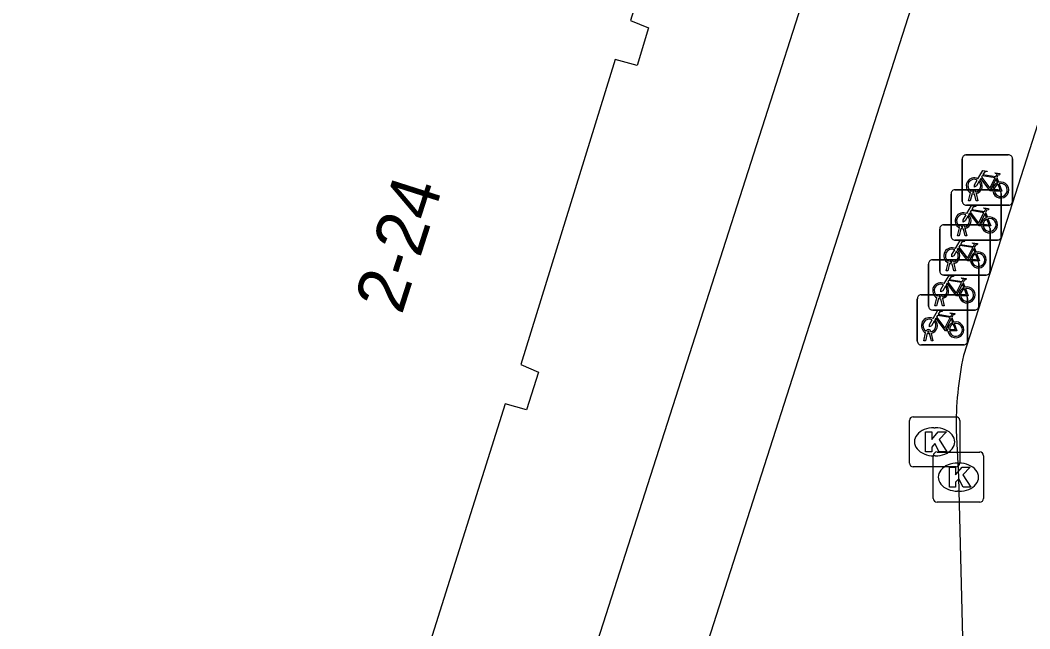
# Model space of a CAD drawing. Extents: x 160676 to 161153, y 383244 to 383713.
# Drawn here: x 161088.71 to 161108.8, y 383397.89 to 383410.01 of the extents above; entities that cross this region are included whole.
import ezdxf

# ---------------------------------------------------------------- set-up
doc = ezdxf.new("R2010")
doc.units = 0
for name, color, linetype in [('IMGEO_Fietsenrek', 7, 'Continuous'), ('IMGEO_Fietspad_gesloten', 7, 'Continuous'), ('IMGEO_Kolk', 7, 'Continuous'), ('IMGEO_Pand', 7, 'Continuous'), ('IMGEO_Pand_nummerreeks', 7, 'Continuous'), ('IMGEO_Rijbaan_lokaal_gesloten', 7, 'Continuous')]:
    doc.layers.add(name, color=color, linetype=linetype)

msp = doc.modelspace()

# ---------------------------------------------------------------- linework, layer by layer
at = {"layer": 'IMGEO_Fietsenrek'}
for p, q in [((161107.532, 383407.329), (161108.373, 383407.329)), ((161108.373, 383407.329), (161107.532, 383407.329)), ((161107.457, 383406.404), (161107.457, 383407.245)), ((161107.457, 383407.245), (161107.457, 383406.404)), ((161108.457, 383407.254), (161108.457, 383406.413)), ((161108.457, 383406.413), (161108.457, 383407.254)), ((161108.144, 383406.878), (161108.18, 383406.783)), ((161107.234, 383405.708), (161107.234, 383406.549)), ((161107.234, 383406.549), (161107.234, 383405.708)), ((161107.309, 383406.633), (161108.15, 383406.633)), ((161108.15, 383406.633), (161107.309, 383406.633)), ((161107.584, 383406.413), (161107.623, 383406.573)), ((161107.653, 383406.561), (161107.618, 383406.413)), ((161107.695, 383406.585), (161107.694, 383406.589)), ((161107.736, 383406.413), (161107.702, 383406.555)), ((161107.726, 383406.596), (161107.727, 383406.589)), ((161107.734, 383406.559), (161107.769, 383406.413)), ((161108.234, 383406.558), (161108.234, 383405.717)), ((161108.234, 383405.717), (161108.234, 383406.558)), ((161108.382, 383406.329), (161107.541, 383406.329)), ((161107.541, 383406.329), (161108.382, 383406.329)), ((161107.618, 383406.413), (161107.584, 383406.413)), ((161107.769, 383406.413), (161107.736, 383406.413)), ((161107.921, 383406.182), (161107.957, 383406.087)), ((161107.085, 383405.937), (161107.926, 383405.937)), ((161107.926, 383405.937), (161107.085, 383405.937)), ((161107.472, 383405.889), (161107.471, 383405.893)), ((161107.503, 383405.9), (161107.504, 383405.893)), ((161107.01, 383405.012), (161107.01, 383405.853)), ((161107.01, 383405.853), (161107.01, 383405.012)), ((161107.361, 383405.717), (161107.4, 383405.877)), ((161107.395, 383405.717), (161107.361, 383405.717)), ((161107.43, 383405.865), (161107.395, 383405.717)), ((161107.513, 383405.717), (161107.479, 383405.859)), ((161107.511, 383405.863), (161107.546, 383405.717)), ((161107.546, 383405.717), (161107.513, 383405.717)), ((161108.01, 383405.862), (161108.01, 383405.021)), ((161108.01, 383405.021), (161108.01, 383405.862)), ((161108.159, 383405.633), (161107.318, 383405.633)), ((161107.318, 383405.633), (161108.159, 383405.633)), ((161107.697, 383405.486), (161107.733, 383405.391)), ((161106.787, 383404.315), (161106.787, 383405.156)), ((161106.787, 383405.156), (161106.787, 383404.315)), ((161106.862, 383405.24), (161107.703, 383405.24)), ((161107.703, 383405.24), (161106.862, 383405.24)), ((161107.137, 383405.021), (161107.176, 383405.181)), ((161107.206, 383405.169), (161107.171, 383405.021)), ((161107.248, 383405.193), (161107.247, 383405.197)), ((161107.289, 383405.021), (161107.255, 383405.163)), ((161107.279, 383405.204), (161107.28, 383405.197)), ((161107.287, 383405.167), (161107.322, 383405.021)), ((161107.787, 383405.165), (161107.787, 383404.324)), ((161107.787, 383404.324), (161107.787, 383405.165)), ((161107.935, 383404.937), (161107.094, 383404.937)), ((161107.094, 383404.937), (161107.935, 383404.937)), ((161107.171, 383405.021), (161107.137, 383405.021)), ((161107.322, 383405.021), (161107.289, 383405.021)), ((161107.474, 383404.789), (161107.51, 383404.694)), ((161106.638, 383404.544), (161107.479, 383404.544)), ((161107.479, 383404.544), (161106.638, 383404.544)), ((161106.914, 383404.324), (161106.953, 383404.484)), ((161107.025, 383404.496), (161107.024, 383404.5)), ((161107.056, 383404.507), (161107.057, 383404.5)), ((161106.563, 383403.619), (161106.563, 383404.46)), ((161106.563, 383404.46), (161106.563, 383403.619)), ((161106.948, 383404.324), (161106.914, 383404.324)), ((161106.983, 383404.472), (161106.948, 383404.324)), ((161107.066, 383404.324), (161107.032, 383404.466)), ((161107.064, 383404.47), (161107.099, 383404.324)), ((161107.099, 383404.324), (161107.066, 383404.324)), ((161107.563, 383404.469), (161107.563, 383403.628)), ((161107.563, 383403.628), (161107.563, 383404.469)), ((161107.712, 383404.24), (161106.871, 383404.24)), ((161106.871, 383404.24), (161107.712, 383404.24)), ((161107.25, 383404.093), (161107.286, 383403.998)), ((161106.69, 383403.628), (161106.729, 383403.788)), ((161106.759, 383403.776), (161106.724, 383403.628)), ((161106.801, 383403.8), (161106.8, 383403.804)), ((161106.842, 383403.628), (161106.808, 383403.77)), ((161106.832, 383403.811), (161106.833, 383403.804)), ((161106.84, 383403.774), (161106.875, 383403.628)), ((161107.488, 383403.544), (161106.647, 383403.544)), ((161106.647, 383403.544), (161107.488, 383403.544)), ((161106.724, 383403.628), (161106.69, 383403.628)), ((161106.875, 383403.628), (161106.842, 383403.628))]:
    msp.add_line(p, q, dxfattribs=at)
for points in [[(161107.77, 383406.855), (161107.865, 383407.019), (161107.951, 383407.005), (161107.953, 383406.996), (161107.897, 383406.985), (161107.87, 383406.94), (161108.126, 383406.899)], [(161108.113, 383406.874), (161107.856, 383406.915), (161107.839, 383406.886), (161108.006, 383406.666), (161108.113, 383406.874)], [(161108.126, 383406.899), (161108.151, 383406.948), (161108.145, 383406.952), (161108.122, 383406.956), (161108.11, 383406.963), (161108.109, 383406.966), (161108.111, 383406.971), (161108.206, 383406.956), (161108.208, 383406.946), (161108.198, 383406.933), (161108.186, 383406.927), (161108.172, 383406.933), (161108.144, 383406.878)], [(161107.791, 383406.803), (161107.739, 383406.713), (161107.699, 383406.688), (161107.7, 383406.735), (161107.755, 383406.829)], [(161108.066, 383406.611), (161108.016, 383406.611), (161107.825, 383406.862), (161107.806, 383406.83)], [(161108.161, 383406.776), (161108.131, 383406.853), (161108.022, 383406.635), (161108.065, 383406.635)], [(161108.095, 383406.635), (161108.215, 383406.634), (161108.171, 383406.748)], [(161108.191, 383406.755), (161108.246, 383406.61), (161108.096, 383406.61)], [(161107.547, 383406.159), (161107.642, 383406.323), (161107.728, 383406.309), (161107.73, 383406.3), (161107.674, 383406.289), (161107.647, 383406.244), (161107.903, 383406.203)], [(161107.568, 383406.107), (161107.516, 383406.017), (161107.476, 383405.992), (161107.477, 383406.039), (161107.532, 383406.133)], [(161107.843, 383405.915), (161107.793, 383405.915), (161107.602, 383406.166), (161107.583, 383406.134)], [(161107.89, 383406.178), (161107.633, 383406.219), (161107.616, 383406.19), (161107.783, 383405.97), (161107.89, 383406.178)], [(161107.938, 383406.08), (161107.908, 383406.157), (161107.799, 383405.939), (161107.842, 383405.939)], [(161107.903, 383406.203), (161107.928, 383406.252), (161107.922, 383406.256), (161107.899, 383406.26), (161107.887, 383406.267), (161107.886, 383406.27), (161107.888, 383406.275), (161107.983, 383406.26), (161107.985, 383406.25), (161107.975, 383406.237), (161107.963, 383406.231), (161107.949, 383406.237), (161107.921, 383406.182)], [(161107.872, 383405.939), (161107.992, 383405.938), (161107.948, 383406.052)], [(161107.968, 383406.059), (161108.023, 383405.914), (161107.873, 383405.914)], [(161107.323, 383405.463), (161107.418, 383405.627), (161107.504, 383405.613), (161107.506, 383405.604), (161107.45, 383405.593), (161107.423, 383405.548), (161107.679, 383405.507)], [(161107.666, 383405.482), (161107.409, 383405.523), (161107.392, 383405.494), (161107.559, 383405.274), (161107.666, 383405.482)], [(161107.679, 383405.507), (161107.704, 383405.556), (161107.698, 383405.56), (161107.675, 383405.564), (161107.663, 383405.571), (161107.662, 383405.574), (161107.664, 383405.579), (161107.759, 383405.564), (161107.761, 383405.554), (161107.751, 383405.541), (161107.739, 383405.535), (161107.725, 383405.541), (161107.697, 383405.486)], [(161107.344, 383405.411), (161107.292, 383405.321), (161107.252, 383405.296), (161107.253, 383405.343), (161107.308, 383405.437)], [(161107.619, 383405.219), (161107.569, 383405.219), (161107.378, 383405.47), (161107.359, 383405.438)], [(161107.714, 383405.384), (161107.684, 383405.461), (161107.575, 383405.243), (161107.618, 383405.243)], [(161107.648, 383405.243), (161107.768, 383405.242), (161107.724, 383405.356)], [(161107.744, 383405.363), (161107.799, 383405.218), (161107.649, 383405.218)], [(161107.1, 383404.766), (161107.195, 383404.93), (161107.281, 383404.916), (161107.283, 383404.907), (161107.227, 383404.896), (161107.2, 383404.851), (161107.456, 383404.81)], [(161107.456, 383404.81), (161107.481, 383404.859), (161107.475, 383404.863), (161107.452, 383404.867), (161107.44, 383404.874), (161107.439, 383404.877), (161107.441, 383404.882), (161107.536, 383404.867), (161107.538, 383404.857), (161107.528, 383404.844), (161107.516, 383404.838), (161107.502, 383404.844), (161107.474, 383404.789)], [(161107.121, 383404.714), (161107.069, 383404.624), (161107.029, 383404.599), (161107.03, 383404.646), (161107.085, 383404.74)], [(161107.396, 383404.522), (161107.346, 383404.522), (161107.155, 383404.773), (161107.136, 383404.741)], [(161107.443, 383404.785), (161107.186, 383404.826), (161107.169, 383404.797), (161107.336, 383404.577), (161107.443, 383404.785)], [(161107.491, 383404.687), (161107.461, 383404.764), (161107.352, 383404.546), (161107.395, 383404.546)], [(161107.425, 383404.546), (161107.545, 383404.545), (161107.501, 383404.659)], [(161107.521, 383404.666), (161107.576, 383404.521), (161107.426, 383404.521)], [(161106.876, 383404.07), (161106.971, 383404.234), (161107.057, 383404.22), (161107.059, 383404.211), (161107.003, 383404.2), (161106.976, 383404.155), (161107.232, 383404.114)], [(161107.172, 383403.826), (161107.122, 383403.826), (161106.931, 383404.077), (161106.912, 383404.045)], [(161107.219, 383404.089), (161106.962, 383404.13), (161106.945, 383404.101), (161107.112, 383403.881), (161107.219, 383404.089)], [(161107.232, 383404.114), (161107.257, 383404.163), (161107.251, 383404.167), (161107.228, 383404.171), (161107.216, 383404.178), (161107.215, 383404.181), (161107.217, 383404.186), (161107.312, 383404.171), (161107.314, 383404.161), (161107.304, 383404.148), (161107.292, 383404.142), (161107.278, 383404.148), (161107.25, 383404.093)], [(161106.897, 383404.018), (161106.845, 383403.928), (161106.805, 383403.903), (161106.806, 383403.95), (161106.861, 383404.044)], [(161107.267, 383403.991), (161107.237, 383404.068), (161107.128, 383403.85), (161107.171, 383403.85)], [(161107.201, 383403.85), (161107.321, 383403.849), (161107.277, 383403.963)], [(161107.297, 383403.97), (161107.352, 383403.825), (161107.202, 383403.825)]]:
    msp.add_lwpolyline(points, dxfattribs=at)
for centre, radius, start, end in [((161107.535, 383407.251), 0.0779, 92.4484, 184.2845), ((161107.535, 383407.251), 0.0779, 92.4484, 184.2845), ((161108.379, 383407.251), 0.0779, 2.4484, 94.2845), ((161108.379, 383407.251), 0.0779, 2.4484, 94.2845), ((161107.697, 383406.714), 0.159, 62.6766, 242.1369), ((161107.697, 383406.714), 0.129, 63.3192, 238.903), ((161107.697, 383406.714), 0.129, 283.6043, 43.4302), ((161107.697, 383406.714), 0.159, 283.5766, 46.6042), ((161108.224, 383406.63), 0.159, 113.3408, 178.3217), ((161108.224, 383406.63), 0.159, 187.0065, 105.7708), ((161108.224, 383406.63), 0.129, 113.923, 177.9556), ((161108.224, 383406.63), 0.129, 188.6715, 104.5883), ((161107.312, 383406.555), 0.0779, 92.4484, 184.2845), ((161107.312, 383406.555), 0.0779, 92.4484, 184.2845), ((161107.677, 383406.585), 0.0499, 12.8025, 158.6934), ((161107.697, 383406.714), 0.159, 253.9967, 271.7867), ((161107.677, 383406.585), 0.0174, 12.8025, 163.4502), ((161107.697, 383406.714), 0.129, 253.415, 269.0204), ((161108.156, 383406.555), 0.0779, 2.4484, 94.2845), ((161108.156, 383406.555), 0.0779, 2.4484, 94.2845), ((161107.535, 383406.407), 0.0779, 182.4484, 274.2845), ((161107.535, 383406.407), 0.0779, 182.4484, 274.2845), ((161108.379, 383406.407), 0.0779, 272.4484, 4.2845), ((161108.379, 383406.407), 0.0779, 272.4484, 4.2845), ((161107.474, 383406.018), 0.159, 62.6766, 242.1369), ((161107.474, 383406.018), 0.129, 63.3192, 238.903), ((161107.474, 383406.018), 0.129, 283.6043, 43.4302), ((161107.474, 383406.018), 0.159, 283.5766, 46.6042), ((161108.001, 383405.934), 0.159, 187.0065, 105.7708), ((161107.088, 383405.859), 0.0779, 92.4484, 184.2845), ((161107.088, 383405.859), 0.0779, 92.4484, 184.2845), ((161107.454, 383405.889), 0.0499, 12.8025, 158.6934), ((161107.454, 383405.889), 0.0174, 12.8025, 163.4502), ((161107.474, 383406.018), 0.129, 253.415, 269.0204), ((161108.001, 383405.934), 0.159, 113.3408, 178.3217), ((161108.001, 383405.934), 0.129, 113.923, 177.9556), ((161108.001, 383405.934), 0.129, 188.6715, 104.5883), ((161107.932, 383405.859), 0.0779, 2.4484, 94.2845), ((161107.932, 383405.859), 0.0779, 2.4484, 94.2845), ((161107.312, 383405.711), 0.0779, 182.4484, 274.2845), ((161107.312, 383405.711), 0.0779, 182.4484, 274.2845), ((161107.474, 383406.018), 0.159, 253.9967, 271.7867), ((161108.156, 383405.711), 0.0779, 272.4484, 4.2845), ((161108.156, 383405.711), 0.0779, 272.4484, 4.2845), ((161107.25, 383405.322), 0.159, 62.6766, 242.1369), ((161107.25, 383405.322), 0.129, 63.3192, 238.903), ((161107.25, 383405.322), 0.129, 283.6043, 43.4302), ((161107.25, 383405.322), 0.159, 283.5766, 46.6042), ((161107.777, 383405.238), 0.159, 113.3408, 178.3217), ((161107.777, 383405.238), 0.159, 187.0065, 105.7708), ((161107.777, 383405.238), 0.129, 113.923, 177.9556), ((161107.777, 383405.238), 0.129, 188.6715, 104.5883), ((161106.865, 383405.162), 0.0779, 92.4484, 184.2845), ((161106.865, 383405.162), 0.0779, 92.4484, 184.2845), ((161107.23, 383405.193), 0.0499, 12.8025, 158.6934), ((161107.25, 383405.322), 0.159, 253.9967, 271.7867), ((161107.23, 383405.193), 0.0174, 12.8025, 163.4502), ((161107.25, 383405.322), 0.129, 253.415, 269.0204), ((161107.709, 383405.162), 0.0779, 2.4484, 94.2845), ((161107.709, 383405.162), 0.0779, 2.4484, 94.2845), ((161107.088, 383405.015), 0.0779, 182.4484, 274.2845), ((161107.088, 383405.015), 0.0779, 182.4484, 274.2845), ((161107.932, 383405.015), 0.0779, 272.4484, 4.2845), ((161107.932, 383405.015), 0.0779, 272.4484, 4.2845), ((161107.027, 383404.625), 0.159, 62.6766, 242.1369), ((161107.027, 383404.625), 0.129, 63.3192, 238.903), ((161107.027, 383404.625), 0.129, 283.6043, 43.4302), ((161107.027, 383404.625), 0.159, 283.5766, 46.6042), ((161107.554, 383404.541), 0.159, 113.3408, 178.3217), ((161107.554, 383404.541), 0.159, 187.0065, 105.7708), ((161106.641, 383404.466), 0.0779, 92.4484, 184.2845), ((161106.641, 383404.466), 0.0779, 92.4484, 184.2845), ((161107.007, 383404.496), 0.0499, 12.8025, 158.6934), ((161107.007, 383404.496), 0.0174, 12.8025, 163.4502), ((161107.027, 383404.625), 0.129, 253.415, 269.0204), ((161107.554, 383404.541), 0.129, 113.923, 177.9556), ((161107.554, 383404.541), 0.129, 188.6715, 104.5883), ((161107.485, 383404.466), 0.0779, 2.4484, 94.2845), ((161107.485, 383404.466), 0.0779, 2.4484, 94.2845), ((161106.865, 383404.318), 0.0779, 182.4484, 274.2845), ((161106.865, 383404.318), 0.0779, 182.4484, 274.2845), ((161107.027, 383404.625), 0.159, 253.9967, 271.7867), ((161107.709, 383404.318), 0.0779, 272.4484, 4.2845), ((161107.709, 383404.318), 0.0779, 272.4484, 4.2845), ((161106.803, 383403.929), 0.159, 62.6766, 242.1369), ((161106.803, 383403.929), 0.129, 63.3192, 238.903), ((161106.803, 383403.929), 0.129, 283.6043, 43.4302), ((161106.803, 383403.929), 0.159, 283.5766, 46.6042), ((161107.33, 383403.845), 0.159, 113.3408, 178.3217), ((161107.33, 383403.845), 0.159, 187.0065, 105.7708), ((161107.33, 383403.845), 0.129, 113.923, 177.9556), ((161107.33, 383403.845), 0.129, 188.6715, 104.5883), ((161106.783, 383403.8), 0.0499, 12.8025, 158.6934), ((161106.803, 383403.929), 0.159, 253.9967, 271.7867), ((161106.783, 383403.8), 0.0174, 12.8025, 163.4502), ((161106.803, 383403.929), 0.129, 253.415, 269.0204), ((161106.641, 383403.622), 0.0779, 182.4484, 274.2845), ((161106.641, 383403.622), 0.0779, 182.4484, 274.2845), ((161107.485, 383403.622), 0.0779, 272.4484, 4.2845), ((161107.485, 383403.622), 0.0779, 272.4484, 4.2845)]:
    msp.add_arc(centre, radius, start, end, dxfattribs=at)
at = {"layer": 'IMGEO_Fietspad_gesloten'}
for points in [[(161118.548, 383454.992), (161111.242, 383432.14), (161095.589, 383383.263), (161087.624, 383358.486)], [(161101.56, 383395.014), (161113.225, 383431.432), (161120.279, 383453.425)]]:
    msp.add_lwpolyline(points, dxfattribs=at)
at = {"layer": 'IMGEO_Kolk'}
for p, q in [((161106.481, 383402.115), (161107.333, 383402.115)), ((161106.406, 383401.189), (161106.406, 383402.041)), ((161106.894, 383401.895), (161106.919, 383401.895)), ((161107.407, 383402.041), (161107.407, 383401.189)), ((161106.88, 383400.486), (161106.88, 383401.338)), ((161106.917, 383401.335), (161106.892, 383401.335)), ((161106.955, 383401.412), (161107.807, 383401.412)), ((161107.881, 383401.338), (161107.881, 383400.486)), ((161107.333, 383401.115), (161106.481, 383401.115)), ((161107.368, 383401.192), (161107.393, 383401.192)), ((161107.391, 383400.632), (161107.366, 383400.632)), ((161107.807, 383400.412), (161106.955, 383400.412))]:
    msp.add_line(p, q, dxfattribs=at)
for points in [[(161106.481, 383402.115), (161107.333, 383402.115)], [(161106.406, 383401.189), (161106.406, 383402.041)], [(161107.407, 383402.041), (161107.407, 383401.189)], [(161106.727, 383401.815), (161106.85, 383401.815), (161106.85, 383401.664), (161106.98, 383401.815), (161107.144, 383401.815), (161106.998, 383401.664), (161107.151, 383401.415), (161106.999, 383401.415), (161106.914, 383401.579), (161106.85, 383401.512), (161106.85, 383401.415), (161106.727, 383401.415), (161106.727, 383401.815)], [(161106.88, 383400.486), (161106.88, 383401.338)], [(161106.955, 383401.412), (161107.807, 383401.412)], [(161107.881, 383401.338), (161107.881, 383400.486)], [(161107.333, 383401.115), (161106.481, 383401.115)], [(161107.201, 383401.112), (161107.324, 383401.112), (161107.324, 383400.961), (161107.454, 383401.112), (161107.618, 383401.112), (161107.472, 383400.961), (161107.625, 383400.712), (161107.473, 383400.712), (161107.388, 383400.876), (161107.324, 383400.809), (161107.324, 383400.712), (161107.201, 383400.712), (161107.201, 383401.112)], [(161107.807, 383400.412), (161106.955, 383400.412)]]:
    msp.add_lwpolyline(points, dxfattribs=at)
for centre, start, end in [((161106.483, 383402.039), 91.552, 178.448), ((161106.483, 383402.039), 91.552, 178.448), ((161107.331, 383402.039), 1.552, 88.448), ((161107.331, 383402.039), 1.552, 88.448), ((161106.957, 383401.336), 91.552, 178.448), ((161106.957, 383401.336), 91.552, 178.448), ((161107.805, 383401.336), 1.552, 88.448), ((161107.805, 383401.336), 1.552, 88.448), ((161106.483, 383401.191), 181.552, 268.448), ((161106.483, 383401.191), 181.552, 268.448), ((161107.331, 383401.191), 271.552, 358.448), ((161107.331, 383401.191), 271.552, 358.448), ((161106.957, 383400.488), 181.552, 268.448), ((161106.957, 383400.488), 181.552, 268.448), ((161107.805, 383400.488), 271.552, 358.448), ((161107.805, 383400.488), 271.552, 358.448)]:
    msp.add_arc(centre, 0.0765, start, end, dxfattribs=at)
for centre, major_axis, ratio, start_param, end_param in [((161106.893, 383401.615), (-0.387, 0.002), 0.722429, 4.712389, 7.853982), ((161106.918, 383401.615), (-0.39, 0.002), 0.717154, 1.570796, 4.712389), ((161107.367, 383400.912), (-0.387, 0.002), 0.722429, 4.712389, 7.853982), ((161107.392, 383400.912), (-0.39, 0.002), 0.717154, 1.570796, 4.712389)]:
    msp.add_ellipse(centre, major_axis=major_axis, ratio=ratio, start_param=start_param, end_param=end_param, dxfattribs=at)
at = {"layer": 'IMGEO_Pand'}
msp.add_lwpolyline([(161102.732, 383416.074), (161100.856, 383410.009), (161101.21, 383409.861), (161100.985, 383409.109), (161100.551, 383409.232), (161098.673, 383403.152), (161099.024, 383403.003), (161098.784, 383402.249), (161098.363, 383402.374), (161096.446, 383396.303), (161096.832, 383396.154), (161096.591, 383395.395), (161096.117, 383395.508), (161094.252, 383389.433), (161094.631, 383389.285), (161094.386, 383388.509), (161093.924, 383388.651), (161092.076, 383382.563)], dxfattribs=at)
at = {"layer": 'IMGEO_Rijbaan_lokaal_gesloten'}
for points in [[(161123.228, 383452.452), (161107.605, 383403.724), (161107.479, 383403.331)], [(161107.334, 383401.845), (161107.381, 383400.912), (161107.574, 383393.19), (161107.563, 383393.154)]]:
    msp.add_lwpolyline(points, dxfattribs=at)
msp.add_arc((161114.401, 383401.906), 7.067, 168.3629, 180.4908, dxfattribs=at)

# ---------------------------------------------------------------- texts
at = {"layer": 'IMGEO_Pand_nummerreeks'}
msp.add_text('2-24', height=1, rotation=72.2487, dxfattribs=at).set_placement((161096.3, 383404.129))

doc.saveas('drawing.dxf')
